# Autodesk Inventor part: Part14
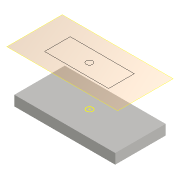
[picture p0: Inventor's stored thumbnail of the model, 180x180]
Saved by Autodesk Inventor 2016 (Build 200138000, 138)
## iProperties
Created: 2015-05
Part Number: Part14
Material: Generic
Document SubType Name: Modeling
Designer: Sandeep
Density: 1 g/cm^3
Appearance: Default
Author: Sandeep
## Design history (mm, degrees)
sketch "Sketch1"
  geometry: L1 (-100, 50)-(100, 50); L2 (100, 50)-(100, -50); L3 (100, -50)-(-100, -50); L4 (-100, -50)-(-100, 50); 1 further point
  constraints: 8 end point, 2 parallel, 1 horizontal, 1 perpendicular
  dimensions: "d0" = 100 distance from line of point (0, 0) L2; "d1" = 200 distance of L1.start L1.end; "d2" = 50 distance from line of point (0, 0) L1; "d3" = 100 distance of L1.end L2.end
extrude "Extrusion1" new body sketch "Sketch1" distance "d4" = 20; taper "d5" = 0 deg
workplane "Work Plane1"
sketch "Sketch2"
  geometry: C1 r 6.35 at (-0.807, -0.346) reference; 1 further point
body "Solid1"
